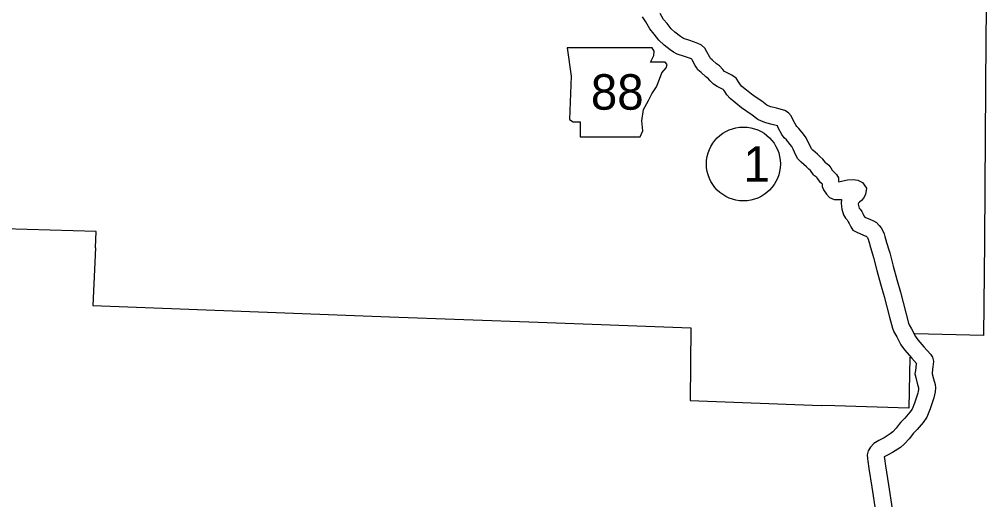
# Model space of a CAD drawing. Extents: x -939622 to -934245, y 1383184 to 1385301.
# Drawn here: x -936405.2 to -936353.4, y 1384156 to 1384181.7 of the extents above; entities that cross this region are included whole.
import ezdxf

# ---------------------------------------------------------------- set-up
doc = ezdxf.new("R2010")
doc.units = 0
for name, color, linetype in [('10', 7, 'Continuous'), ('21', 7, 'Continuous'), ('27', 7, 'Continuous'), ('8', 7, 'Continuous')]:
    doc.layers.add(name, color=color, linetype=linetype)

msp = doc.modelspace()

# ---------------------------------------------------------------- linework, layer by layer
at = {"layer": '10'}
for points in [[(-936362.656, 1384173.366), (-936362.818, 1384173.594), (-936362.904, 1384173.667), (-936363.037, 1384173.784), (-936363.319, 1384174.034), (-936363.487, 1384174.22), (-936363.602, 1384174.413), (-936363.754, 1384174.731), (-936363.823, 1384174.879), (-936363.903, 1384174.987), (-936364.102, 1384175.232), (-936364.221, 1384175.347), (-936364.354, 1384175.526), (-936364.541, 1384175.875), (-936364.592, 1384175.98), (-936364.865, 1384176.057), (-936365.209, 1384176.147), (-936365.442, 1384176.235), (-936365.629, 1384176.332), (-936365.94, 1384176.563), (-936366.231, 1384176.753), (-936366.513, 1384176.953), (-936366.811, 1384177.192), (-936367.122, 1384177.444), (-936367.304, 1384177.645), (-936367.4, 1384177.816), (-936367.454, 1384177.9), (-936367.496, 1384177.93), (-936367.817, 1384178.086), (-936368.017, 1384178.212), (-936368.185, 1384178.404), (-936368.283, 1384178.507), (-936368.418, 1384178.602), (-936368.676, 1384178.848), (-936368.842, 1384178.981), (-936368.928, 1384179.105), (-936368.996, 1384179.222), (-936369.15, 1384179.517), (-936369.171, 1384179.551), (-936369.25, 1384179.591), (-936369.563, 1384179.706), (-936369.954, 1384179.831), (-936370.158, 1384179.934), (-936370.327, 1384180.064), (-936370.656, 1384180.314), (-936370.932, 1384180.569), (-936371.195, 1384180.897), (-936371.425, 1384181.174), (-936371.636, 1384181.552), (-936371.804, 1384181.817)], [(-936362.01, 1384174.011), (-936362.149, 1384174.207), (-936362.317, 1384174.349), (-936362.442, 1384174.459), (-936362.684, 1384174.674), (-936362.758, 1384174.756), (-936362.807, 1384174.838), (-936362.941, 1384175.118), (-936363.047, 1384175.342), (-936363.191, 1384175.538), (-936363.439, 1384175.843), (-936363.543, 1384175.943), (-936363.592, 1384176.009), (-936363.738, 1384176.281), (-936363.856, 1384176.529), (-936364.001, 1384176.68), (-936364.196, 1384176.804), (-936364.63, 1384176.926), (-936364.935, 1384177.006), (-936365.075, 1384177.059), (-936365.152, 1384177.098), (-936365.425, 1384177.302), (-936365.724, 1384177.498), (-936365.972, 1384177.673), (-936366.246, 1384177.893), (-936366.501, 1384178.099), (-936366.568, 1384178.173), (-936366.629, 1384178.282), (-936366.793, 1384178.533), (-936367.034, 1384178.706), (-936367.38, 1384178.875), (-936367.426, 1384178.904), (-936367.519, 1384179.01), (-936367.692, 1384179.193), (-936367.846, 1384179.3), (-936368.083, 1384179.526), (-936368.174, 1384179.599), (-936368.209, 1384179.659), (-936368.365, 1384179.956), (-936368.479, 1384180.148), (-936368.662, 1384180.303), (-936368.892, 1384180.418), (-936369.27, 1384180.557), (-936369.612, 1384180.667), (-936369.678, 1384180.7), (-936369.78, 1384180.779), (-936370.077, 1384181.004), (-936370.272, 1384181.185), (-936370.498, 1384181.466), (-936370.679, 1384181.685), (-936370.862, 1384182.012)], [(-936362.01, 1384174.011), (-936361.83, 1384173.882), (-936361.728, 1384173.739), (-936361.666, 1384173.611), (-936361.657, 1384173.602), (-936361.545, 1384173.51), (-936361.42, 1384173.374), (-936361.325, 1384173.197), (-936361.311, 1384173.036), (-936361.305, 1384172.978), (-936361.095, 1384173.042), (-936360.833, 1384173.087), (-936360.526, 1384173.113), (-936360.282, 1384173.065), (-936360.026, 1384172.955), (-936359.817, 1384172.643), (-936359.874, 1384172.299), (-936359.976, 1384172.116), (-936360.095, 1384171.986), (-936360.188, 1384171.902), (-936360.245, 1384171.846), (-936360.252, 1384171.835), (-936360.268, 1384171.804), (-936360.266, 1384171.785), (-936360.255, 1384171.717), (-936360.217, 1384171.579), (-936360.217, 1384171.579), (-936360.156, 1384171.513), (-936360.064, 1384171.385), (-936359.998, 1384171.25), (-936359.954, 1384171.166), (-936359.916, 1384171.095), (-936359.611, 1384170.957), (-936359.448, 1384170.886), (-936359.291, 1384170.797), (-936359.141, 1384170.648), (-936359.034, 1384170.512), (-936358.938, 1384170.358), (-936358.88, 1384170.205), (-936358.833, 1384170.048), (-936358.798, 1384169.929), (-936358.773, 1384169.84)], [(-936362.656, 1384173.366), (-936362.492, 1384173.249), (-936362.459, 1384173.157), (-936362.331, 1384172.994), (-936362.235, 1384172.913), (-936362.2, 1384172.884), (-936362.198, 1384172.86), (-936362.186, 1384172.736), (-936362.119, 1384172.557), (-936361.963, 1384172.329), (-936361.802, 1384172.15), (-936361.555, 1384172.037), (-936361.15, 1384172.039), (-936361.175, 1384171.841), (-936361.16, 1384171.67), (-936361.135, 1384171.523), (-936361.051, 1384171.217), (-936360.937, 1384171.032), (-936360.854, 1384170.941), (-936360.838, 1384170.92), (-936360.802, 1384170.845), (-936360.749, 1384170.744), (-936360.658, 1384170.577), (-936360.545, 1384170.398), (-936360.332, 1384170.295), (-936359.976, 1384170.134), (-936359.851, 1384170.08), (-936359.84, 1384170.074), (-936359.815, 1384170.049), (-936359.772, 1384169.993), (-936359.748, 1384169.956), (-936359.733, 1384169.916), (-936359.696, 1384169.792), (-936359.664, 1384169.683), (-936359.64, 1384169.598)], [(-936358.776, 1384169.847), (-936358.576, 1384169.177), (-936358.387, 1384168.463), (-936358.198, 1384167.751), (-936358.006, 1384167.07), (-936357.715, 1384165.965), (-936357.567, 1384165.416), (-936357.535, 1384165.324), (-936357.408, 1384165.11), (-936357.198, 1384164.704), (-936357.159, 1384164.644), (-936357.066, 1384164.526), (-936356.741, 1384164.145), (-936356.384, 1384163.754), (-936356.277, 1384163.588), (-936356.229, 1384163.369), (-936356.245, 1384163.193), (-936356.263, 1384163.082), (-936356.307, 1384162.748), (-936356.31, 1384162.733), (-936356.303, 1384162.702), (-936356.238, 1384162.421), (-936356.148, 1384162.13), (-936356.125, 1384161.948), (-936356.137, 1384161.734), (-936356.174, 1384161.571), (-936356.21, 1384161.41), (-936356.41, 1384160.818), (-936356.58, 1384160.379), (-936356.79, 1384160.084), (-936357.109, 1384159.712), (-936357.317, 1384159.499), (-936357.364, 1384159.444), (-936357.536, 1384159.208), (-936357.79, 1384158.941), (-936358.004, 1384158.756), (-936358.424, 1384158.488), (-936358.722, 1384158.328), (-936358.867, 1384158.247), (-936358.872, 1384158.242), (-936358.856, 1384158.163), (-936358.797, 1384157.761), (-936358.637, 1384156.749), (-936358.449, 1384155.453)], [(-936359.638, 1384169.591), (-936359.443, 1384168.933), (-936359.257, 1384168.233), (-936359.066, 1384167.513), (-936358.874, 1384166.833), (-936358.585, 1384165.733), (-936358.428, 1384165.15), (-936358.355, 1384164.942), (-936358.195, 1384164.673), (-936357.978, 1384164.254), (-936357.894, 1384164.123), (-936357.763, 1384163.955), (-936357.415, 1384163.549), (-936357.147, 1384163.254), (-936357.154, 1384163.214), (-936357.199, 1384162.874), (-936357.224, 1384162.702), (-936357.181, 1384162.505), (-936357.108, 1384162.187), (-936357.031, 1384161.938), (-936357.028, 1384161.916), (-936357.031, 1384161.86), (-936357.051, 1384161.77), (-936357.078, 1384161.654), (-936357.256, 1384161.124), (-936357.379, 1384160.809), (-936357.5, 1384160.638), (-936357.773, 1384160.32), (-936357.98, 1384160.108), (-936358.069, 1384160.004), (-936358.228, 1384159.786), (-936358.412, 1384159.593), (-936358.543, 1384159.48), (-936358.879, 1384159.265), (-936359.153, 1384159.118), (-936359.425, 1384158.967), (-936359.613, 1384158.768), (-936359.722, 1384158.57), (-936359.776, 1384158.356), (-936359.774, 1384158.165), (-936359.743, 1384158.009), (-936359.687, 1384157.625), (-936359.527, 1384156.614), (-936359.341, 1384155.336)]]:
    msp.add_lwpolyline(points, dxfattribs=at)
at = {"layer": '21'}
msp.add_lwpolyline([(-936375.851, 1384180.161), (-936375.623, 1384178.638), (-936375.724, 1384176.329), (-936375.521, 1384176.202), (-936375.141, 1384176.202), (-936375.141, 1384175.39), (-936371.943, 1384175.39), (-936371.791, 1384175.72), (-936371.842, 1384176.253), (-936371.766, 1384176.862), (-936371.487, 1384177.344), (-936371.309, 1384177.699), (-936371.055, 1384178.08), (-936370.903, 1384178.486), (-936370.776, 1384178.816), (-936370.548, 1384179.095), (-936370.497, 1384179.273), (-936370.598, 1384179.4), (-936371.385, 1384179.4), (-936371.207, 1384179.755), (-936371.182, 1384179.983), (-936371.287, 1384180.159)], close=True, dxfattribs=at)
at = {"layer": '27'}
msp.add_circle((-936366.408, 1384173.941), 1.98, dxfattribs=at)
at = {"layer": '8'}
for points in [[(-936353.386, 1384183.759), (-936353.428, 1384180.621), (-936353.48, 1384172.71), (-936353.508, 1384169.764)], [(-936401.095, 1384169.442), (-936401.071, 1384170.316), (-936409.692, 1384170.569), (-936413.645, 1384170.692), (-936413.545, 1384174.689), (-936417.603, 1384174.712), (-936418.745, 1384174.734)], [(-936353.508, 1384169.764), (-936353.549, 1384164.742), (-936357.233, 1384164.832)], [(-936401.095, 1384169.442), (-936401.24, 1384166.357), (-936393.291, 1384166.045), (-936385.366, 1384165.745), (-936377.397, 1384165.457), (-936369.223, 1384165.156), (-936369.263, 1384161.262), (-936362.247, 1384161.006)], [(-936357.493, 1384163.583), (-936357.554, 1384160.853), (-936361.507, 1384160.975), (-936362.247, 1384161.006)]]:
    msp.add_lwpolyline(points, dxfattribs=at)

# ---------------------------------------------------------------- texts
at = {"layer": '21'}
msp.add_text('88', height=1.9008, dxfattribs=at).set_placement((-936374.578, 1384176.849))
at = {"layer": '27'}
msp.add_text('1', height=1.901, dxfattribs=at).set_placement((-936366.408, 1384172.991))

doc.saveas('drawing.dxf')
